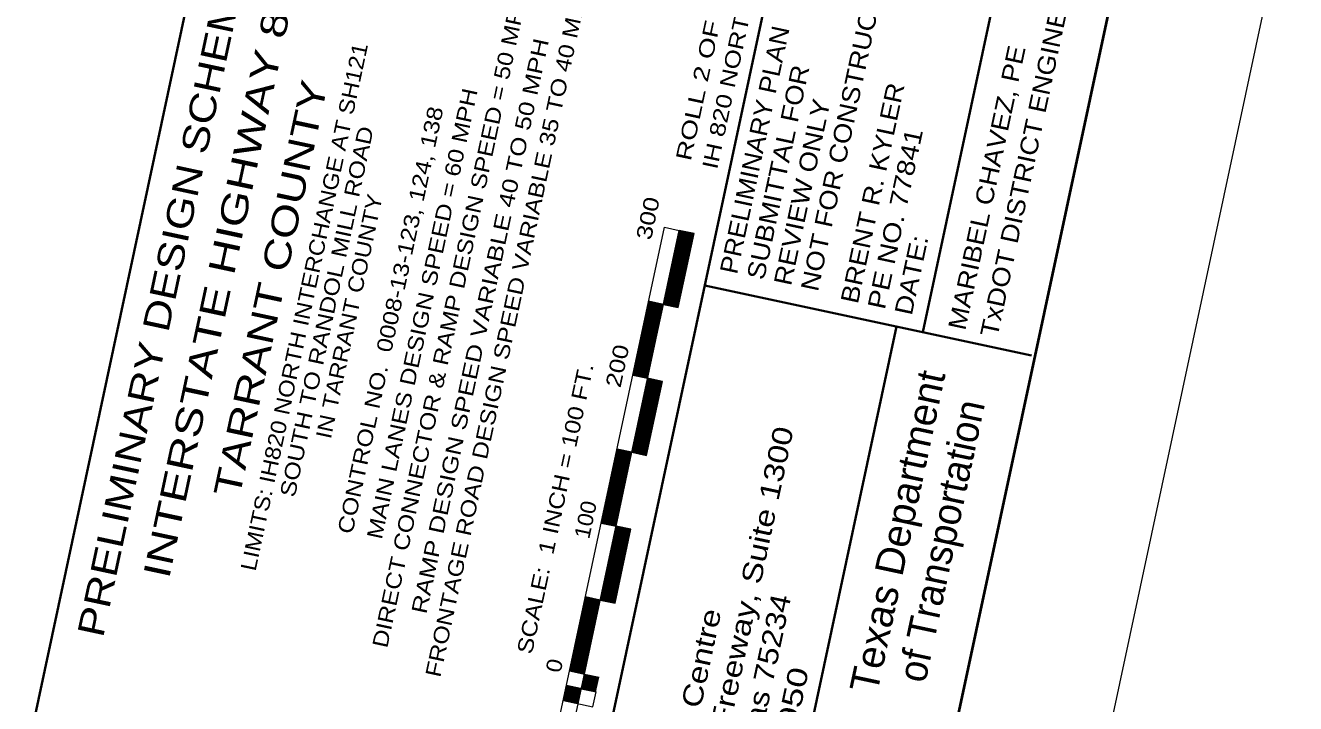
# Model space of a CAD drawing. Extents: x 2363411 to 2369126, y 6976878 to 6988319.
# Drawn here: x 2368286 to 2369126, y 6986908 to 6987356 of the extents above; entities that cross this region are included whole.
import ezdxf
from ezdxf.enums import TextEntityAlignment as Align

# ---------------------------------------------------------------- set-up
doc = ezdxf.new("R2010")
doc.units = 0
doc.header["$LTSCALE"] = 2
doc.layers.add('61', color=7, linetype='Continuous')
doc.layers.add('62', color=7, linetype='Continuous', lineweight=13)
doc.layers.add('63', color=7, linetype='Continuous', lineweight=13)

msp = doc.modelspace()

# ---------------------------------------------------------------- linework, layer by layer
at = {"layer": '62', "lineweight": 35}
for p, q in [((2368287.795, 6986877.338), (2368423.826, 6987513.987)), ((2368788.776, 6987433.781), (2368652.739, 6986797.1)), ((2368933.065, 6987402.951), (2368879.741, 6987153.387)), ((2368951.569, 6987138.04), (2368735.452, 6987184.215)), ((2368862.364, 6987157.099), (2368779.65, 6986769.983))]:
    msp.add_line(p, q, dxfattribs=at)
at = {"layer": '62'}
for p, q in [((2369126.202, 6987466.173), (2366932.108, 6977197.487)), ((2368625.251, 6986831.589), (2368708.843, 6987222.813)), ((2368635.032, 6986829.5), (2368718.624, 6987220.723)), ((2368708.436, 6987171.764), (2368718.886, 6987220.666)), ((2368708.843, 6987222.813), (2368718.624, 6987220.723)), ((2368708.925, 6987171.659), (2368719.374, 6987220.562)), ((2368709.414, 6987171.554), (2368719.863, 6987220.458)), ((2368709.903, 6987171.449), (2368720.353, 6987220.353)), ((2368710.391, 6987171.345), (2368720.841, 6987220.248)), ((2368710.881, 6987171.24), (2368721.33, 6987220.144)), ((2368718.624, 6987220.723), (2368728.404, 6987218.633)), ((2368711.37, 6987171.136), (2368721.818, 6987220.04)), ((2368711.859, 6987171.031), (2368722.307, 6987219.936)), ((2368712.348, 6987170.928), (2368722.797, 6987219.83)), ((2368712.837, 6987170.823), (2368723.285, 6987219.726)), ((2368713.326, 6987170.719), (2368723.775, 6987219.622)), ((2368713.815, 6987170.614), (2368724.264, 6987219.518)), ((2368714.303, 6987170.508), (2368724.753, 6987219.413)), ((2368714.792, 6987170.405), (2368725.242, 6987219.308)), ((2368715.282, 6987170.3), (2368725.731, 6987219.203)), ((2368715.771, 6987170.195), (2368726.22, 6987219.099)), ((2368716.26, 6987170.091), (2368726.709, 6987218.994)), ((2368716.749, 6987169.986), (2368727.199, 6987218.891)), ((2368717.239, 6987169.883), (2368727.687, 6987218.785)), ((2368717.728, 6987169.778), (2368728.177, 6987218.682)), ((2368688.328, 6987124.925), (2368698.776, 6987173.827)), ((2368688.817, 6987124.821), (2368699.266, 6987173.723)), ((2368689.306, 6987124.716), (2368699.755, 6987173.618)), ((2368689.794, 6987124.611), (2368700.244, 6987173.514)), ((2368690.283, 6987124.506), (2368700.734, 6987173.408)), ((2368690.773, 6987124.402), (2368701.222, 6987173.304)), ((2368691.262, 6987124.298), (2368701.711, 6987173.201)), ((2368691.751, 6987124.193), (2368702.2, 6987173.095)), ((2368692.24, 6987124.088), (2368702.689, 6987172.991)), ((2368692.729, 6987123.985), (2368703.179, 6987172.886)), ((2368693.218, 6987123.879), (2368703.668, 6987172.782)), ((2368693.707, 6987123.776), (2368704.156, 6987172.678)), ((2368694.196, 6987123.67), (2368704.645, 6987172.573)), ((2368694.685, 6987123.567), (2368705.133, 6987172.468)), ((2368695.174, 6987123.461), (2368705.623, 6987172.364)), ((2368695.663, 6987123.357), (2368706.112, 6987172.26)), ((2368696.152, 6987123.253), (2368706.6, 6987172.156)), ((2368696.641, 6987123.148), (2368707.09, 6987172.05)), ((2368697.13, 6987123.044), (2368707.579, 6987171.947)), ((2368697.619, 6987122.94), (2368708.068, 6987171.841)), ((2368698.394, 6987173.908), (2368708.174, 6987171.819)), ((2368708.174, 6987171.819), (2368717.955, 6987169.729)), ((2368687.659, 6987073.931), (2368698.108, 6987122.833)), ((2368687.945, 6987125.007), (2368697.726, 6987122.917)), ((2368688.148, 6987073.828), (2368698.597, 6987122.73)), ((2368688.637, 6987073.722), (2368699.086, 6987122.626)), ((2368689.126, 6987073.618), (2368699.575, 6987122.522)), ((2368689.615, 6987073.514), (2368700.064, 6987122.417)), ((2368690.104, 6987073.409), (2368700.552, 6987122.312)), ((2368690.593, 6987073.304), (2368701.041, 6987122.209)), ((2368691.082, 6987073.2), (2368701.53, 6987122.103)), ((2368691.571, 6987073.095), (2368702.019, 6987122)), ((2368692.06, 6987072.992), (2368702.509, 6987121.894)), ((2368692.549, 6987072.886), (2368702.997, 6987121.79)), ((2368693.038, 6987072.783), (2368703.486, 6987121.686)), ((2368693.528, 6987072.677), (2368703.976, 6987121.581)), ((2368694.018, 6987072.573), (2368704.466, 6987121.477)), ((2368694.506, 6987072.468), (2368704.955, 6987121.372)), ((2368694.995, 6987072.364), (2368705.444, 6987121.267)), ((2368695.484, 6987072.259), (2368705.932, 6987121.163)), ((2368695.973, 6987072.155), (2368706.422, 6987121.058)), ((2368696.462, 6987072.051), (2368706.911, 6987120.955)), ((2368696.95, 6987071.947), (2368707.4, 6987120.849)), ((2368697.726, 6987122.917), (2368707.505, 6987120.827)), ((2368667.332, 6987027.14), (2368677.78, 6987076.042)), ((2368667.821, 6987027.036), (2368678.269, 6987075.937)), ((2368668.311, 6987026.931), (2368678.759, 6987075.834)), ((2368668.8, 6987026.826), (2368679.248, 6987075.728)), ((2368669.288, 6987026.721), (2368679.738, 6987075.625)), ((2368669.777, 6987026.617), (2368680.226, 6987075.519)), ((2368670.266, 6987026.512), (2368680.715, 6987075.415)), ((2368670.755, 6987026.409), (2368681.203, 6987075.31)), ((2368671.244, 6987026.303), (2368681.693, 6987075.206)), ((2368671.734, 6987026.2), (2368682.182, 6987075.102)), ((2368672.222, 6987026.096), (2368682.671, 6987074.997)), ((2368672.71, 6987025.99), (2368683.16, 6987074.893)), ((2368673.199, 6987025.886), (2368683.649, 6987074.789)), ((2368673.689, 6987025.781), (2368684.138, 6987074.683)), ((2368674.178, 6987025.677), (2368684.627, 6987074.58)), ((2368674.666, 6987025.573), (2368685.116, 6987074.474)), ((2368675.156, 6987025.467), (2368685.605, 6987074.37)), ((2368675.645, 6987025.364), (2368686.094, 6987074.265)), ((2368676.134, 6987025.259), (2368686.583, 6987074.161)), ((2368676.623, 6987025.155), (2368687.072, 6987074.057)), ((2368677.496, 6987076.104), (2368687.276, 6987074.013)), ((2368687.276, 6987074.013), (2368697.057, 6987071.923)), ((2368667.047, 6987027.2), (2368676.828, 6987025.11)), ((2368666.757, 6986976.127), (2368677.206, 6987025.029)), ((2368667.245, 6986976.023), (2368677.695, 6987024.925)), ((2368667.735, 6986975.917), (2368678.185, 6987024.82)), ((2368668.223, 6986975.813), (2368678.673, 6987024.716)), ((2368668.713, 6986975.708), (2368679.162, 6987024.613)), ((2368669.202, 6986975.604), (2368679.652, 6987024.508)), ((2368669.69, 6986975.499), (2368680.139, 6987024.403)), ((2368670.18, 6986975.396), (2368680.629, 6987024.298)), ((2368670.669, 6986975.291), (2368681.117, 6987024.194)), ((2368671.158, 6986975.186), (2368681.606, 6987024.09)), ((2368671.647, 6986975.082), (2368682.096, 6987023.986)), ((2368672.135, 6986974.977), (2368682.584, 6987023.881)), ((2368672.625, 6986974.872), (2368683.074, 6987023.776)), ((2368673.115, 6986974.768), (2368683.563, 6987023.671)), ((2368673.604, 6986974.663), (2368684.052, 6987023.568)), ((2368674.093, 6986974.559), (2368684.542, 6987023.462)), ((2368674.582, 6986974.454), (2368685.03, 6987023.358)), ((2368675.072, 6986974.35), (2368685.52, 6987023.253)), ((2368675.56, 6986974.246), (2368686.009, 6987023.149)), ((2368676.049, 6986974.142), (2368686.498, 6987023.045)), ((2368676.828, 6987025.11), (2368686.608, 6987023.021)), ((2368646.502, 6986929.319), (2368656.95, 6986978.222)), ((2368646.99, 6986929.215), (2368657.439, 6986978.118)), ((2368647.48, 6986929.11), (2368657.929, 6986978.012)), ((2368647.969, 6986929.006), (2368658.418, 6986977.909)), ((2368648.457, 6986928.901), (2368658.907, 6986977.803)), ((2368648.947, 6986928.797), (2368659.397, 6986977.7)), ((2368649.436, 6986928.692), (2368659.885, 6986977.595)), ((2368649.924, 6986928.588), (2368660.375, 6986977.49)), ((2368650.414, 6986928.484), (2368660.863, 6986977.386)), ((2368650.903, 6986928.38), (2368661.352, 6986977.281)), ((2368651.392, 6986928.274), (2368661.842, 6986977.176)), ((2368651.881, 6986928.171), (2368662.33, 6986977.072)), ((2368652.37, 6986928.066), (2368662.82, 6986976.967)), ((2368652.859, 6986927.961), (2368663.308, 6986976.864)), ((2368653.348, 6986927.856), (2368663.797, 6986976.759)), ((2368653.837, 6986927.752), (2368664.287, 6986976.655)), ((2368656.598, 6986978.297), (2368666.38, 6986976.208)), ((2368654.326, 6986927.647), (2368664.775, 6986976.55)), ((2368654.815, 6986927.543), (2368665.263, 6986976.446)), ((2368655.304, 6986927.439), (2368665.753, 6986976.342)), ((2368655.793, 6986927.335), (2368666.241, 6986976.236)), ((2368666.38, 6986976.208), (2368676.159, 6986974.117)), ((2368646.149, 6986929.395), (2368655.93, 6986927.305)), ((2368654.033, 6986917.482), (2368656.123, 6986927.264)), ((2368654.523, 6986917.379), (2368656.613, 6986927.159)), ((2368655.011, 6986917.274), (2368657.1, 6986927.055)), ((2368655.5, 6986917.169), (2368657.59, 6986926.952)), ((2368655.929, 6986927.306), (2368665.71, 6986925.216)), ((2368655.93, 6986927.305), (2368665.709, 6986925.216)), ((2368655.989, 6986917.065), (2368658.079, 6986926.846)), ((2368656.478, 6986916.96), (2368658.567, 6986926.742)), ((2368656.967, 6986916.857), (2368659.057, 6986926.637)), ((2368657.456, 6986916.751), (2368659.546, 6986926.533)), ((2368657.945, 6986916.647), (2368660.035, 6986926.429)), ((2368658.435, 6986916.542), (2368660.524, 6986926.325)), ((2368658.923, 6986916.437), (2368661.012, 6986926.22)), ((2368642.163, 6986909.793), (2368644.252, 6986919.574)), ((2368642.652, 6986909.687), (2368644.742, 6986919.468)), ((2368643.143, 6986909.582), (2368645.232, 6986919.364)), ((2368643.631, 6986909.478), (2368645.72, 6986919.259)), ((2368644.059, 6986919.615), (2368653.839, 6986917.524)), ((2368644.12, 6986909.374), (2368646.21, 6986919.155)), ((2368644.61, 6986909.27), (2368646.699, 6986919.051)), ((2368645.098, 6986909.165), (2368647.188, 6986918.945)), ((2368645.587, 6986909.06), (2368647.677, 6986918.841)), ((2368646.075, 6986908.956), (2368648.165, 6986918.736)), ((2368646.564, 6986908.852), (2368648.655, 6986918.632)), ((2368647.054, 6986908.748), (2368649.144, 6986918.527)), ((2368647.542, 6986908.642), (2368649.634, 6986918.424)), ((2368648.032, 6986908.539), (2368650.122, 6986918.319)), ((2368648.521, 6986908.434), (2368650.611, 6986918.214)), ((2368649.009, 6986908.33), (2368651.099, 6986918.109)), ((2368649.499, 6986908.224), (2368651.588, 6986918.005)), ((2368649.987, 6986908.12), (2368652.078, 6986917.9)), ((2368650.477, 6986908.015), (2368652.566, 6986917.796)), ((2368659.412, 6986916.333), (2368661.502, 6986926.115)), ((2368659.901, 6986916.229), (2368661.99, 6986926.011)), ((2368660.39, 6986916.124), (2368662.479, 6986925.907)), ((2368660.88, 6986916.02), (2368662.97, 6986925.801)), ((2368661.368, 6986915.915), (2368663.458, 6986925.697)), ((2368661.857, 6986915.812), (2368663.948, 6986925.592)), ((2368662.346, 6986915.706), (2368664.437, 6986925.488)), ((2368662.835, 6986915.602), (2368664.925, 6986925.384)), ((2368663.325, 6986915.497), (2368665.415, 6986925.279)), ((2368641.97, 6986909.833), (2368651.75, 6986907.743)), ((2368650.966, 6986907.911), (2368653.056, 6986917.692)), ((2368651.455, 6986907.807), (2368653.544, 6986917.587)), ((2368653.839, 6986917.525), (2368663.62, 6986915.436)), ((2368653.84, 6986917.524), (2368663.62, 6986915.434))]:
    msp.add_line(p, q, dxfattribs=at)
at = {"layer": '62', "lineweight": 40}
msp.add_line((2369007.509, 6987389.272), (2366855.207, 6977316.18), dxfattribs=at)
at = {"layer": '62'}
for points in [[(2368717.955, 6987169.729), (2368728.404, 6987218.633), (2368718.624, 6987220.723), (2368708.174, 6987171.819)], [(2368697.726, 6987122.917), (2368708.174, 6987171.819), (2368698.394, 6987173.908), (2368687.945, 6987125.007)], [(2368697.057, 6987071.923), (2368707.505, 6987120.827), (2368697.726, 6987122.917), (2368687.276, 6987074.013)], [(2368676.828, 6987025.11), (2368687.276, 6987074.013), (2368677.496, 6987076.104), (2368667.047, 6987027.2)], [(2368676.159, 6986974.117), (2368686.608, 6987023.021), (2368676.828, 6987025.11), (2368666.38, 6986976.208)], [(2368655.93, 6986927.305), (2368666.38, 6986976.208), (2368656.598, 6986978.297), (2368646.149, 6986929.395)], [(2368661.531, 6986905.653), (2368663.62, 6986915.434), (2368644.059, 6986919.615), (2368641.97, 6986909.833)]]:
    msp.add_lwpolyline(points, close=True, dxfattribs=at)
at = {"layer": '63', "lineweight": 35}
msp.add_line((2368287.795, 6986877.338), (2368423.826, 6987513.987), dxfattribs=at)
at = {"layer": '63'}
msp.add_line((2369126.202, 6987466.173), (2366932.108, 6977197.487), dxfattribs=at)
at = {"layer": '63', "lineweight": 40}
msp.add_line((2369007.509, 6987389.272), (2366855.207, 6977316.18), dxfattribs=at)

# ---------------------------------------------------------------- texts
at = {"layer": '61'}
for s, width, p in [('LIMITS: IH820 NORTH INTERCHANGE AT SH121', 1.15, (2368475.638, 6987169.161)), ('SOUTH TO RANDOL MILL ROAD', 1.2, (2368490.504, 6987165.986)), ('IN TARRANT COUNTY', 1.15, (2368505.369, 6987162.809))]:
    msp.add_text(s, height=10.2, rotation=77.939, dxfattribs=dict(at, width=width)).set_placement(p, align=Align.CENTER)
at = {"layer": '62'}
for s, height, width, p in [('PRELIMINARY DESIGN SCHEMATIC', 17.5, 1.25, (2368337.545, 6986950.723)), ('NOT FOR CONSTRUCTION.', 11.74, 1.15, (2368810.32, 6987179.743)), ('INTERSTATE HIGHWAY 820', 17.5, 1.35, (2368381.168, 6986989.583)), ('TxDOT DISTRICT ENGINEER', 11.74, 1.15, (2368928.993, 6987149.515)), ('PRELIMINARY PLAN', 11.74, 1.1, (2368756.799, 6987191.178)), ('MARIBEL CHAVEZ, PE', 11.74, 1.15, (2368907.733, 6987154.056)), ('SUBMITTAL FOR', 11.74, 1.15, (2368774.639, 6987187.367)), ('TARRANT COUNTY', 17.5, 1.3, (2368427.68, 6987043.323)), ('BRENT R. KYLER', 11.74, 1.15, (2368836.668, 6987171.618)), ('REVIEW ONLY', 11.74, 1.15, (2368792.479, 6987183.555)), ('CONTROL NO.  0008-13-123, 124, 138', 10.2, 1.2, (2368502.474, 6987019.352)), ('PE NO. 77841', 11.74, 1.2, (2368854.503, 6987167.807)), ('DATE: ', 11.74, 1.15, (2368872.336, 6987163.997)), ('3010 LBJ Freeway, Suite 1300', 13.22, 1.25, (2368731.217, 6986793.8)), ('Dallas, Texas 75234', 13.22, 1.2, (2368752.289, 6986789.297)), ('Graystone Centre', 13.22, 1.25, (2368710.144, 6986798.303)), ('972-406-6950', 13.22, 1.35, (2368773.363, 6986784.795))]:
    msp.add_text(s, height=height, rotation=77.939, dxfattribs=dict(at, width=width)).set_placement(p)
for s, height, width, p in [('FRONTAGE ROAD DESIGN SPEED VARIABLE 35 TO 40 MPH', 10.2, 1.2, (2368609.509, 6987153.607)), ('DIRECT CONNECTOR & RAMP DESIGN SPEED = 50 MPH', 10.2, 1.2, (2368571.8, 6987160.767)), ('ROLL 2 OF 4', 10.2, 1.35, (2368737.618, 6987319.718)), ('IH 820 NORTH', 10.2, 1.25, (2368755.732, 6987317.124)), ('RAMP DESIGN SPEED VARIABLE 40 TO 50 MPH', 10.2, 1.25, (2368591.922, 6987156.467)), ('MAIN LANES DESIGN SPEED = 60 MPH', 10.2, 1.2, (2368553.632, 6987164.651)), ('300', 10.2, 1.25, (2368702.885, 6987227.67)), ('200', 10.2, 1.25, (2368682.69, 6987130.045)), ('SCALE:  1 INCH = 100 FT.', 10.2, 1.2, (2368641.632, 6987035.764)), ('Texas Department', 18.76, 1.05, (2368872.111, 6987019.714)), ('100', 10.2, 1.1, (2368661.64, 6987028.359)), ('0', 10.2, 1.15, (2368641.009, 6986931.827))]:
    msp.add_text(s, height=height, rotation=77.939, dxfattribs=dict(at, width=width)).set_placement(p, align=Align.CENTER)
msp.add_text('of Transportation', height=18.76, rotation=77.939, dxfattribs=at).set_placement((2368901.094, 6987013.449), align=Align.CENTER)

doc.saveas('drawing.dxf')
